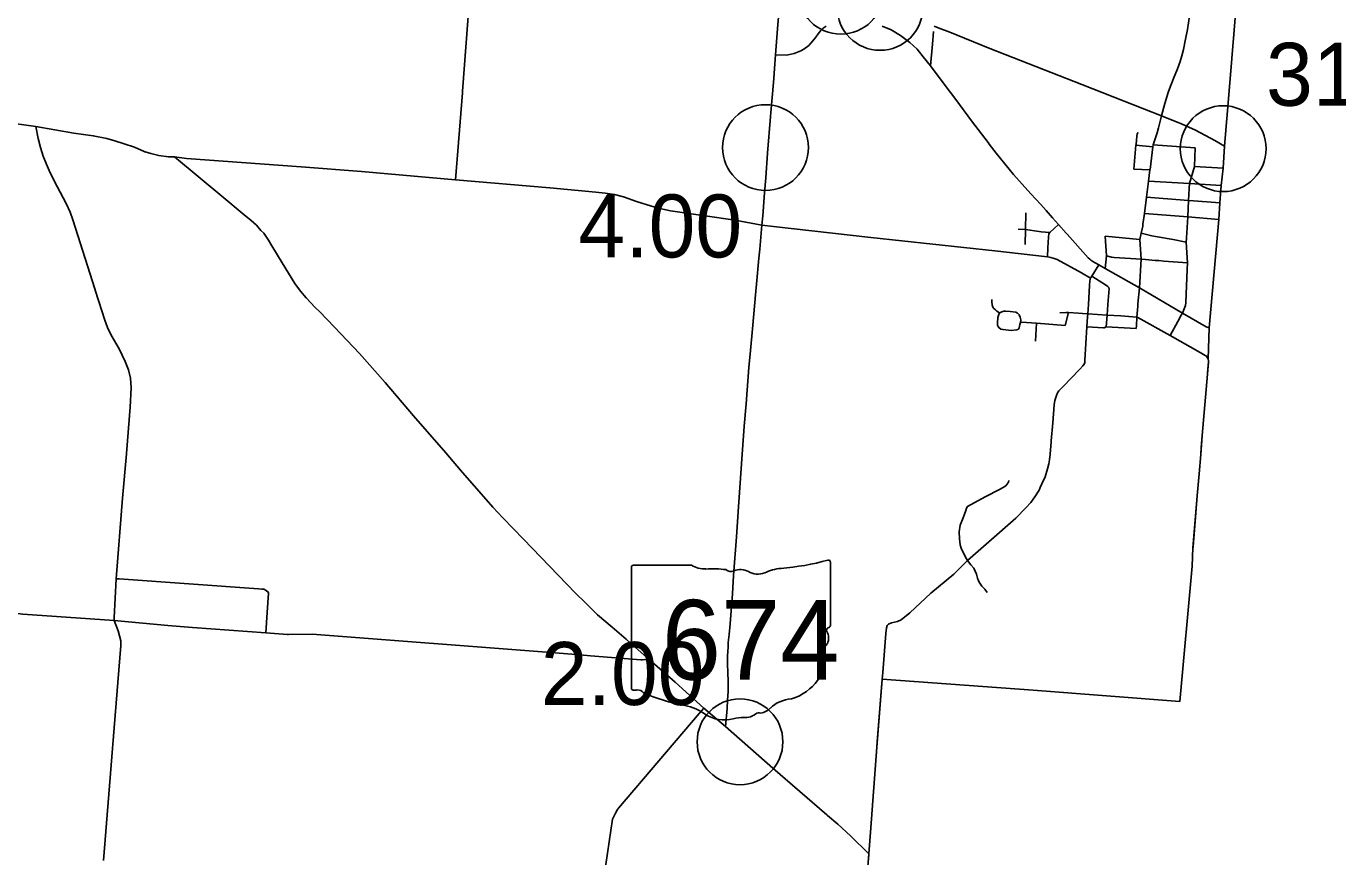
# Model space of a CAD drawing. Extents: x 1729596 to 1934326, y 644115 to 911751.
# Drawn here: x 1863218 to 1886157, y 661397 to 675915 of the extents above; entities that cross this region are included whole.
import ezdxf

# ---------------------------------------------------------------- set-up
doc = ezdxf.new("R2010")
doc.units = 0
for name, color, linetype in [('Default', 7, 'Continuous'), ('GM_X_City_Street', 7, 'Continuous'), ('GM_X_County', 7, 'Continuous'), ('GM_X_County_Road', 7, 'Continuous'), ('GM_X_State_Route', 7, 'Continuous'), ('GM_X_State_Shield', 7, 'Continuous'), ('GM_X_Township_Road', 7, 'Continuous'), ('GM_X_US_Route', 7, 'Continuous')]:
    doc.layers.add(name, color=color, linetype=linetype)

msp = doc.modelspace()

# ---------------------------------------------------------------- linework, layer by layer
at = {"layer": 'Default'}
for centre in [(1877465, 676527), (1878151, 676245), (1876148, 673794), (1884153, 673775), (1875702, 663407)]:
    msp.add_circle(centre, 750, dxfattribs=at)
at = {"layer": 'GM_X_City_Street'}
for points in [[(1883073, 674346), (1883131, 674564), (1883188, 674755), (1883213, 674818), (1883282, 674999), (1883352, 675169), (1883402, 675301), (1883430, 675398), (1883457, 675510), (1883495, 675689), (1883527, 675858), (1883544, 675976), (1883573, 676181), (1883764, 677538), (1883766, 677557)], [(1877208, 675919), (1877157, 675879), (1877117, 675842), (1877068, 675783), (1877026, 675724), (1876949, 675623), (1876904, 675577), (1876819, 675514), (1876766, 675485), (1876710, 675460), (1876649, 675439), (1876595, 675425), (1876516, 675412), (1876324, 675415)], [(1878908, 675378), (1878798, 675515), (1878672, 675632), (1878509, 675752), (1878345, 675851), (1878190, 675916)], [(1879035, 675220), (1879070, 675604), (1879089, 675823)], [(1880041, 673883), (1879748, 674262), (1879476, 674633), (1879291, 674879), (1879035, 675220), (1878908, 675378)], [(1870847, 674748), (1870850, 674781), (1870855, 674853)], [(1883022, 674139), (1883073, 674346)], [(1882629, 673848), (1882629, 673848), (1882643, 673996), (1882649, 674034), (1882664, 674058)], [(1882873, 673410), (1882922, 673808), (1882926, 673843), (1882995, 674036)], [(1882995, 674036), (1883000, 674050), (1883022, 674139)], [(1881405, 672300), (1881272, 672449), (1881166, 672568), (1881054, 672696), (1880964, 672797), (1880791, 672988), (1880488, 673325), (1880183, 673695), (1880062, 673856), (1880041, 673883)], [(1882590, 673419), (1882628, 673834), (1882628, 673838), (1882629, 673848)], [(1882628, 673834), (1882922, 673808)], [(1882926, 673843), (1883665, 673791)], [(1883512, 672224), (1883516, 672304), (1883532, 672581), (1883548, 672869), (1883560, 673079), (1883566, 673165), (1883649, 673466), (1883665, 673791)], [(1882590, 673419), (1882872, 673404)], [(1882750, 672457), (1882775, 672640), (1882813, 672925), (1882848, 673208), (1882872, 673404), (1882873, 673410)], [(1883649, 673466), (1884153, 673436)], [(1882848, 673208), (1883566, 673165), (1884120, 673132)], [(1873383, 672991), (1873504, 672971), (1873662, 672930), (1873894, 672853), (1874153, 672772), (1874300, 672731), (1874486, 672690), (1875618, 672523), (1876085, 672438)], [(1882813, 672925), (1883545, 672869), (1883548, 672869), (1883559, 672868)], [(1883559, 672868), (1884093, 672829)], [(1880690, 672102), (1880696, 672361), (1880703, 672651)], [(1882775, 672640), (1883532, 672581), (1884077, 672538)], [(1875594, 672298), (1875618, 672523)], [(1876085, 672438), (1876287, 672416), (1877992, 672224), (1880157, 671988), (1881078, 671885), (1881136, 671874), (1881181, 671863), (1881252, 671835), (1881672, 671604), (1881832, 671512)], [(1880567, 672370), (1880696, 672361), (1880935, 672325)], [(1881086, 672044), (1881096, 672226), (1881104, 672285), (1881120, 672310), (1881272, 672449)], [(1882690, 671343), (1882719, 671844), (1882698, 672187), (1882721, 672299), (1882746, 672423), (1882750, 672457)], [(1880935, 672325), (1880968, 672320), (1881120, 672310)], [(1881978, 671744), (1881875, 671804), (1881855, 671817), (1881840, 671827), (1881818, 671846), (1881793, 671869), (1881424, 672278), (1881405, 672300)], [(1882089, 671682), (1882111, 671901), (1882086, 672246)], [(1882086, 672246), (1882698, 672187)], [(1882721, 672299), (1882837, 672266), (1882907, 672250), (1883007, 672231), (1883279, 672185), (1883508, 672142)], [(1883524, 671664), (1883530, 671779), (1883508, 672142), (1883511, 672207), (1883512, 672224)], [(1881078, 671885), (1881086, 672044)], [(1882111, 671901), (1882200, 671876), (1882246, 671873)], [(1881837, 671520), (1881857, 671544), (1881978, 671744)], [(1881978, 671744), (1882089, 671682), (1882690, 671343)], [(1882246, 671873), (1882719, 671844), (1882796, 671837)], [(1882796, 671837), (1882962, 671822), (1883025, 671818)], [(1883025, 671818), (1883117, 671811)], [(1883117, 671811), (1883530, 671779)], [(1881782, 670836), (1881786, 670889), (1881795, 671053), (1881816, 671384), (1881821, 671466), (1881832, 671512), (1881837, 671520)], [(1882154, 671338), (1882151, 671350), (1882137, 671367), (1882110, 671385), (1881857, 671544)], [(1883420, 670865), (1883440, 670900), (1883473, 670973), (1883485, 671004), (1883494, 671035), (1883498, 671087), (1883524, 671664)], [(1882106, 670659), (1882124, 670866), (1882136, 671053), (1882156, 671332), (1882154, 671338)], [(1882660, 671024), (1882663, 671065), (1882690, 671343)], [(1882690, 671343), (1883440, 670900), (1883857, 670660), (1883910, 670644)], [(1880105, 671139), (1880105, 671095), (1880115, 671045), (1880122, 671003), (1880144, 670983), (1880170, 670955), (1880196, 670937), (1880222, 670918), (1880241, 670908), (1880248, 670904), (1880280, 670922), (1880316, 670932), (1880354, 670932), (1880426, 670929), (1880528, 670917), (1880554, 670902), (1880584, 670872), (1880602, 670832), (1880611, 670784), (1880609, 670738)], [(1882663, 670822), (1882645, 670832), (1882660, 671024)], [(1880241, 670908), (1880228, 670878), (1880211, 670826), (1880203, 670726), (1880204, 670706)], [(1881297, 670908), (1881409, 670910)], [(1881392, 670685), (1881450, 670911)], [(1881409, 670910), (1881450, 670911), (1881615, 670901), (1881690, 670896)], [(1881690, 670896), (1881786, 670889), (1882124, 670866), (1882364, 670850)], [(1881731, 670044), (1881735, 670079), (1881771, 670662), (1881782, 670836)], [(1882364, 670850), (1882645, 670832)], [(1882629, 670633), (1882638, 670675), (1882645, 670832)], [(1883894, 670037), (1883896, 670058), (1883888, 670099), (1883869, 670135), (1883853, 670151), (1883835, 670162), (1883752, 670214), (1883226, 670506), (1882663, 670822)], [(1883226, 670506), (1883358, 670752), (1883420, 670865)], [(1880204, 670706), (1880204, 670702), (1880205, 670690), (1880218, 670664), (1880228, 670646), (1880264, 670622), (1880302, 670611), (1880446, 670599), (1880544, 670606), (1880572, 670618), (1880587, 670640), (1880599, 670700), (1880609, 670738), (1880625, 670742), (1880890, 670722), (1881392, 670685)], [(1880871, 670410), (1880890, 670722)], [(1881771, 670662), (1882061, 670644)], [(1882061, 670644), (1882074, 670643), (1882106, 670659), (1882629, 670633)], [(1881348, 669611), (1881646, 669921), (1881701, 669978), (1881719, 670005), (1881731, 670037), (1881731, 670044)], [(1883769, 668549), (1883785, 668758), (1883877, 669831), (1883885, 669930)], [(1883885, 669930), (1883889, 669973), (1883894, 670037)], [(1881145, 668651), (1881147, 668666), (1881173, 668984), (1881198, 669299), (1881209, 669374), (1881237, 669461), (1881257, 669507), (1881280, 669540), (1881332, 669595), (1881348, 669611)], [(1879528, 666423), (1879681, 666578), (1880056, 666902), (1880526, 667316), (1880702, 667494), (1880788, 667591), (1880858, 667689), (1880932, 667807), (1880953, 667852), (1880982, 667913), (1881037, 668037), (1881080, 668176), (1881101, 668265), (1881115, 668338), (1881127, 668434), (1881145, 668651)], [(1883625, 666796), (1883626, 666816), (1883700, 667709), (1883733, 668091), (1883760, 668427), (1883769, 668549)], [(1879681, 666578), (1879644, 666635), (1879568, 666794), (1879555, 666847), (1879539, 666955), (1879534, 667075), (1879554, 667192), (1879604, 667319), (1879651, 667452), (1879661, 667491), (1879679, 667520), (1879988, 667688), (1880254, 667824), (1880350, 667881), (1880386, 667925), (1880409, 667977)], [(1883609, 666477), (1883625, 666796)], [(1878198, 664617), (1878254, 665297), (1878264, 665398), (1878277, 665438), (1878302, 665465), (1878350, 665488), (1878454, 665511), (1878519, 665540), (1878671, 665663), (1879039, 666006), (1879444, 666338), (1879528, 666423)], [(1880026, 666017), (1879983, 666072), (1879930, 666129), (1879894, 666177), (1879876, 666218), (1879857, 666268), (1879837, 666336), (1879814, 666389), (1879790, 666441), (1879740, 666498), (1879681, 666578)], [(1873723, 665190), (1874117, 664838), (1874566, 664446), (1875071, 663996), (1875446, 663673)], [(1872907, 664924), (1873089, 664908), (1873966, 664840), (1873995, 664841), (1874024, 664843), (1874064, 664841)], [(1874064, 664841), (1874117, 664838)], [(1878103, 663403), (1878189, 664504), (1878198, 664617)], [(1880829, 664311), (1883392, 664110)], [(1873562, 662223), (1873575, 662245), (1874988, 663903), (1875071, 663996)], [(1877958, 661450), (1877984, 661828), (1878096, 663311), (1878103, 663403)]]:
    msp.add_lwpolyline(points, dxfattribs=at)
at = {"layer": 'GM_X_County'}
msp.add_lwpolyline([(1884479, 677480), (1884260, 674783), (1884177, 673820), (1884153, 673436), (1884120, 673132), (1884093, 672829), (1884077, 672538), (1883910, 670644), (1883888, 670099), (1883896, 670058), (1883889, 669973), (1883877, 669831), (1883785, 668758), (1883760, 668427), (1883733, 668091), (1883700, 667709), (1883625, 666796), (1883609, 666477), (1883392, 664110), (1880829, 664311), (1878189, 664504), (1878096, 663311), (1877984, 661828), (1877958, 661450), (1877649, 657393)], dxfattribs=at)
at = {"layer": 'GM_X_County_Road'}
for points in [[(1862373, 674304), (1862840, 674240), (1863384, 674164), (1864053, 674044), (1864390, 674002), (1864630, 673951), (1864765, 673913), (1864929, 673857), (1865112, 673799), (1865280, 673728), (1865294, 673721), (1865297, 673720)], [(1864489, 671105), (1864473, 671154), (1864377, 671452), (1864120, 672259), (1864031, 672532), (1863985, 672663), (1863920, 672805), (1863863, 672918), (1863756, 673115), (1863634, 673354), (1863566, 673518), (1863515, 673643), (1863470, 673796), (1863426, 673955), (1863384, 674164)], [(1865297, 673720), (1865397, 673692), (1865536, 673653), (1865708, 673630), (1865811, 673635)], [(1865811, 673635), (1866022, 673605), (1868024, 673455), (1869083, 673378), (1870724, 673229), (1872375, 673088), (1873180, 673017), (1873341, 672998), (1873383, 672991)], [(1865811, 673635), (1866638, 672945), (1867028, 672621)], [(1867028, 672621), (1867153, 672517), (1867245, 672439), (1867323, 672345), (1867374, 672295), (1867453, 672176), (1867515, 672079), (1867696, 671779), (1867917, 671415), (1868012, 671286), (1868112, 671166), (1868274, 671000)], [(1864970, 668444), (1865034, 669256), (1865054, 669593), (1865039, 669765), (1865007, 669911), (1864949, 670055), (1864841, 670275), (1864704, 670513), (1864640, 670647), (1864594, 670775), (1864489, 671105)], [(1868274, 671000), (1868347, 670926), (1868610, 670653), (1869044, 670197), (1869498, 669689), (1869989, 669106), (1870557, 668457), (1870814, 668157), (1871379, 667510), (1871553, 667320), (1871913, 666946), (1872824, 666007), (1872995, 665840), (1873212, 665623), (1873465, 665411), (1873709, 665202), (1873723, 665190)], [(1864756, 665581), (1864756, 665582), (1864793, 666258), (1864900, 667663), (1864970, 668440), (1864970, 668444)], [(1855462, 666252), (1856483, 666179), (1856930, 666146), (1857651, 666095), (1859326, 665971), (1860259, 665910), (1861859, 665794), (1863158, 665640), (1864334, 665557)], [(1864334, 665557), (1864338, 665557), (1864754, 665527)], [(1864569, 661334), (1864755, 663649), (1864875, 665092), (1864872, 665174), (1864827, 665345), (1864754, 665527), (1864756, 665581)], [(1864754, 665527), (1865692, 665442), (1866128, 665403), (1867408, 665311), (1867785, 665280), (1867804, 665280)], [(1867804, 665280), (1868217, 665290), (1872391, 664968), (1872907, 664924)], [(1872662, 659716), (1873068, 660509), (1873300, 660936), (1873325, 661064), (1873471, 662054), (1873523, 662158), (1873562, 662223)]]:
    msp.add_lwpolyline(points, dxfattribs=at)
at = {"layer": 'GM_X_State_Route'}
for points in [[(1876241, 674405), (1876285, 674929), (1876324, 675415), (1876365, 675943), (1876379, 676135)], [(1876085, 672438), (1876104, 672599), (1876133, 673004), (1876156, 673263), (1876184, 673694), (1876236, 674339), (1876241, 674405)], [(1876033, 671862), (1876048, 672019), (1876085, 672438)], [(1875487, 664672), (1875486, 664715), (1875485, 664901), (1875488, 664990), (1875492, 665060), (1875497, 665142), (1875510, 665281), (1875529, 665471), (1875569, 665993), (1875591, 666316), (1875642, 666989), (1875675, 667514), (1875726, 668267), (1875776, 668925), (1875808, 669315), (1875858, 669948), (1875886, 670245), (1875919, 670627), (1875980, 671283), (1875989, 671409), (1876033, 671862)], [(1875475, 663988), (1875476, 663991), (1875485, 664137), (1875492, 664285), (1875493, 664406), (1875487, 664672)], [(1875446, 663673), (1875446, 663673), (1875475, 663988)], [(1877958, 661450), (1877635, 661761), (1877411, 661966), (1877232, 662119), (1877219, 662130), (1876275, 662947), (1875446, 663673)], [(1877949, 661344), (1877958, 661450)]]:
    msp.add_lwpolyline(points, dxfattribs=at)
at = {"layer": 'GM_X_State_Shield'}
for p, q in [((1873802, 666458), (1873802, 664345)), ((1874856, 666494), (1873836, 666494)), ((1877283, 665441), (1877283, 666547)), ((1877282, 665441), (1877283, 665441))]:
    msp.add_line(p, q, dxfattribs=at)
for centre, major_axis, start_param, end_param in [((1873842, 666462), (40.3, 0), 1.712693, 3.28349), ((1875098, 666740), (391, 0), 4.042523, 4.731795), ((1875228, 665308), (1404, 0), 1.404758, 1.657858), ((1875547, 666473), (113, 0), 3.836095, 5.185415), ((1875712, 666229), (235, 0), 0.950623, 2.079405), ((1876514, 665849), (743, 0), 1.699011, 2.107814), ((1876043, 669375), (3691, 0), 4.814394, 5.042369), ((1877244, 666551), (38.7, 0), 6.141152, 7.989035), ((1876015, 666564), (282, 0), 4.081561, 5.145723), ((1877274, 665360), (60, 0), 1.883978, 3.671073), ((1876892, 665220), (360, 0), 5.934695, 6.695948), ((1877241, 665437), (41.5, 0), 5.05454, 6.418171), ((1877421, 664979), (262, 0), 2.387724, 3.262537), ((1876250, 664838), (923, 0), 5.101752, 6.440018), ((1873842, 664340), (40.7, 0), 3.00124, 4.508301), ((1873849, 664556), (310, 0), 4.665946, 4.897461), ((1873912, 664223), (112, 0), 0.519207, 1.627899), ((1875325, 666121), (2665, 0), 4.195997, 4.488961), ((1876639, 663751), (506, 0), 1.647645, 2.488434), ((1874531, 663395), (834, 0), 0.823519, 1.323587), ((1875433, 664212), (529, 0), 4.026481, 4.996735), ((1875777, 664054), (282, 0), 4.691044, 5.507374), ((1876032, 663849), (79.4, 0), 1.147584, 2.315152), ((1875998, 664140), (298, 0), 4.937069, 5.64225), ((1875738, 663482), (435, 0), 1.495662, 1.94098)]:
    msp.add_ellipse(centre, major_axis=major_axis, ratio=0.8, start_param=start_param, end_param=end_param, dxfattribs=at)
at = {"layer": 'GM_X_Township_Road'}
for points in [[(1870855, 674853), (1870962, 676320)], [(1870724, 673229), (1870847, 674748)], [(1864793, 666258), (1864845, 666255)], [(1864845, 666255), (1867282, 666082), (1867340, 666075), (1867372, 666075), (1867416, 666052), (1867449, 666025), (1867457, 666003), (1867434, 665667), (1867408, 665311)]]:
    msp.add_lwpolyline(points, dxfattribs=at)
at = {"layer": 'GM_X_US_Route'}
for points in [[(1879096, 675915), (1879195, 675877)], [(1879195, 675877), (1879341, 675821), (1880074, 675527), (1881678, 674897), (1882775, 674463), (1883073, 674346), (1883438, 674204), (1883667, 674098), (1884006, 673920), (1884177, 673820)]]:
    msp.add_lwpolyline(points, dxfattribs=at)

# ---------------------------------------------------------------- texts
at = {"layer": 'Default'}
for s, p in [('31.23', (1884903, 674525)), ('4.00', (1872877, 671874)), ('2.00', (1872218, 664050))]:
    msp.add_text(s, height=1100, dxfattribs=at).set_placement(p)
at = {"layer": 'GM_X_State_Shield'}
msp.add_text('674', height=1392.2, dxfattribs=at).set_placement((1874334, 664494))

doc.saveas('drawing.dxf')
